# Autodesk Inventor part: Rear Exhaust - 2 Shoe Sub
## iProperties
Created: 2008-02
Part Number: Rear Exhaust - 2 Shoe Sub
Document SubType Name: Modeling
Designer: Autodesk, Inc.
Mass: 51.7894 g
Surface Area: 821.929 cm^2
Volume: 51.7894 cm^3
Density: 1 g/cm^3
Author: Autodesk, Inc.
